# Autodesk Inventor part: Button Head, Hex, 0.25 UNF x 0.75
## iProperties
Author: Administrator
Shininess: 25.0
PropertySet Name: _Private Model Information
Created: 2001-03
Part Number: Button Head, Hex, 0.25 UNF x 0.75
Material: Steel, Mild
Description: Button Head, Hex, 0.25 UNF x 0.75
Document SubType Name: Modeling
Designer: Administrator
Control State: 0
Master: False
Checked Out: False
PropertySet Name: Design Tracking Control
Density: 7.86
Volumn: 1.0470389527034538
Area: 8.192112949038872
PropertySet Name: Model Information
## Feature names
1. Revolution1
2. Hex [Extrusion]
3. Chamfer1
